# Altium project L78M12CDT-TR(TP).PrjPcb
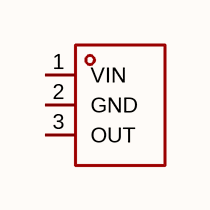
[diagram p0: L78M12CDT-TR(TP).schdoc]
1 sheet, 1 parts. Net scope: global (net labels, ports and power ports of the same name join across sheets).

## Sheet L78M12CDT-TR(TP).schdoc
size 127 x 101 mm

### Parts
U?  l78m12cdt-tr(tp)  [TO-252-2_L6.6-W6.1-P4.60-LS10.0-BR-CW]  (value not drawn)

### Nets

Not connected (* = marked no-connect by the designer): U? 1(VIN) 2(GND) 3(OUT)

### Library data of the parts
U? = l78m12cdt-tr(tp): 输出极性:正极;工作电压:35V;输出电压:12V;输出电流:1A;电源纹波抑制比(PSRR):61dB@(120Hz);输出类型:固定;; Manufacturer: TECH PUBLIC(台舟); AddInBom: yes; ModelId: 2bfbfbb77002446c96d8a76a432e0188; ModelTransform: 246.80147,383.8575,0,90,0,0,-31.302,0.003,0; Output Configuration: 正极; Voltage - Supply: 35V; Output Voltage: 12V; Output Current: 1A; Voltage Dropout: 1V@(300mA); standby current: 8mA; Noise: 42uV; Output Type: 固定; Number of Outputs: 1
